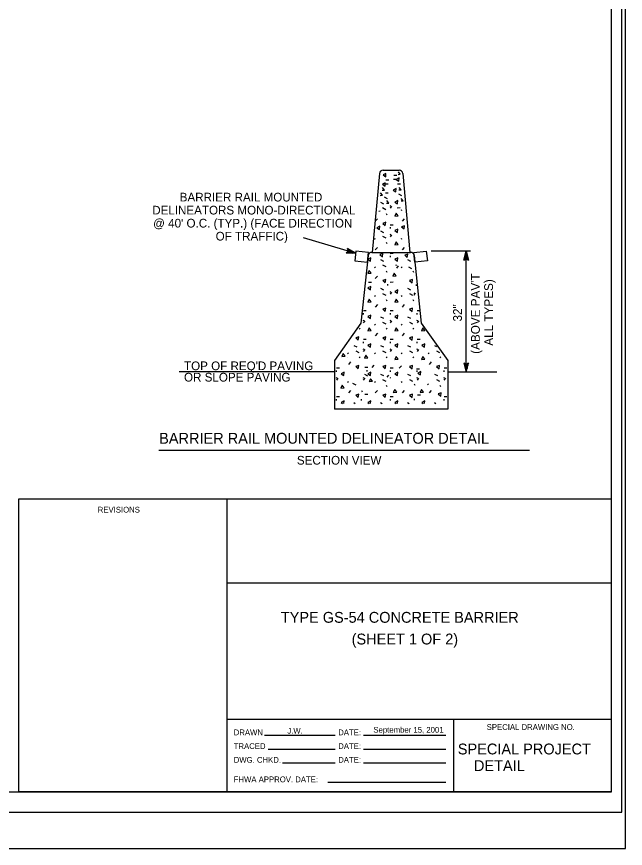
# Model space of a CAD drawing. Extents: x 504255 to 505955, y 659986 to 661086.
# Drawn here: x 505553 to 505955, y 659986 to 660536 of the extents above; entities that cross this region are included whole.
import ezdxf

# ---------------------------------------------------------------- set-up
doc = ezdxf.new("R2010")
doc.units = 0
for name, color, linetype in [('Level 62', 7, 'Continuous'), ('Level1', 7, 'Continuous'), ('Level3', 7, 'Continuous'), ('Level63', 7, 'Continuous')]:
    doc.layers.add(name, color=color, linetype=linetype)

msp = doc.modelspace()

# ---------------------------------------------------------------- linework, layer by layer
at = {"layer": 'Level 62'}
msp.add_lwpolyline([(505955.48, 661086.39), (504255.48, 661086.39), (504255.48, 659986.39), (505955.48, 659986.39)], close=True, dxfattribs=at)
at = {"layer": 'Level1'}
for p, q in [((505792.97, 660432.68), (505788.18, 660380.52)), ((505808.33, 660432.68), (505813.12, 660380.52)), ((505742.45, 660390.42), (505777.23, 660379.88)), ((505853.11, 660381.38), (505827.17, 660381.38)), ((505850.32, 660301.52), (505850.32, 660381.38)), ((505823.29, 660328.72), (505823.29, 660328.72)), ((505838.06, 660307.81), (505838.06, 660307.81)), ((505647.02, 660249.61), (505892.16, 660249.61)), ((505946.29, 660217.21), (505554.37, 660217.21)), ((505554.37, 660217.21), (505554.37, 660023.67)), ((505692.05, 660217.21), (505692.05, 660023.67)), ((505692.05, 660161.99), (505946.29, 660161.99)), ((505692.05, 660071.92), (505946.29, 660071.92)), ((505841.81, 660071.92), (505841.81, 660023.67)), ((505716.88, 660061.14), (505763.62, 660061.14)), ((505782.31, 660061.14), (505836.74, 660061.14)), ((505719.48, 660052.06), (505763.62, 660052.06)), ((505782.31, 660052.06), (505836.74, 660052.06)), ((505728.82, 660042.97), (505763.62, 660042.97)), ((505782.31, 660042.97), (505836.74, 660042.97)), ((505758.94, 660030.06), (505836.74, 660030.06)), ((505946.29, 660023.67), (505554.37, 660023.67))]:
    msp.add_line(p, q, dxfattribs=at)
for points in [[(504257.9, 660010.3), (505953.07, 660010.3), (505953.07, 661062.47), (504257.9, 661062.47), (504257.9, 660010.3)], [(504327.92, 660023.67), (505946.29, 660023.67), (505946.29, 661038.56), (504327.92, 661038.56), (504327.92, 660023.67)], [(505795.35, 660434.83), (505805.95, 660434.83)], [(505771.02, 660380.2), (505777.23, 660379.88), (505771.91, 660383.05), (505772.44, 660382.37), (505773.43, 660382.07), (505772.32, 660381.89), (505775.22, 660381.01), (505772.5, 660381.31), (505774.92, 660380.06), (505772.03, 660380.93), (505772.85, 660380.16), (505771.86, 660380.47), (505771.02, 660380.2), (505772.43, 660381.34), (505771.91, 660383.05)], [(505787.84, 660380.52), (505813.46, 660380.52)], [(505848.81, 660375.4), (505850.32, 660381.38), (505851.83, 660375.4), (505851.33, 660376.11), (505851.33, 660377.14), (505850.82, 660376.15), (505850.82, 660379.13), (505850.32, 660376.48), (505849.82, 660379.13), (505849.82, 660376.15), (505849.31, 660377.14), (505849.31, 660376.11), (505848.81, 660375.4), (505850.32, 660376.4), (505851.83, 660375.4)], [(505785.46, 660378.4), (505780.7, 660333.61)], [(505815.84, 660378.4), (505820.6, 660333.61)], [(505780.7, 660333.61), (505763.25, 660308.92)], [(505820.6, 660333.61), (505838.06, 660308.92)], [(505763.25, 660308.92), (505763.25, 660276.83)], [(505838.06, 660308.92), (505838.06, 660276.83)], [(505848.81, 660307.5), (505850.32, 660301.52), (505851.83, 660307.5), (505851.33, 660306.79), (505851.33, 660305.76), (505850.82, 660306.76), (505850.82, 660303.77), (505850.32, 660306.43), (505849.82, 660303.77), (505849.82, 660306.76), (505849.31, 660305.76), (505849.31, 660306.79), (505848.81, 660307.5), (505850.32, 660306.5), (505851.83, 660307.5)], [(505838.06, 660276.83), (505763.25, 660276.83)]]:
    msp.add_lwpolyline(points, dxfattribs=at)
for points in [[(505776.7, 660374.82), (505784.99, 660373.96), (505785.68, 660380.52), (505777.39, 660381.38)], [(505824.61, 660374.82), (505816.32, 660373.96), (505815.62, 660380.52), (505823.91, 660381.38)], [(505771.89, 660310.84), (505771.89, 660310.83), (505771.9, 660310.84)]]:
    msp.add_lwpolyline(points, close=True, dxfattribs=at)
for centre, start_param, end_param in [((505795.35, 660432.46), 4.712389, 6.192092), ((505805.95, 660432.46), 3.232686, 4.712389), ((505787.84, 660378.15), 4.712389, 6.178514), ((505813.46, 660378.15), 3.24706, 4.712389)]:
    msp.add_ellipse(centre, major_axis=(-2.39, 0), ratio=0.99, start_param=start_param, end_param=end_param, dxfattribs=at)
at = {"layer": 'Level3'}
for p, q in [((505804.37, 660431.35), (505802.41, 660431.32)), ((505798.81, 660425.58), (505796.85, 660425.55)), ((505799.08, 660428.33), (505797.12, 660428.3)), ((505804.1, 660428.78), (505802.14, 660428.74)), ((505806.79, 660425.67), (505804.83, 660425.64)), ((505798.81, 660419.73), (505796.85, 660419.69)), ((505805.62, 660419.24), (505807.58, 660418.09)), ((505793.7, 660413.71), (505795.7, 660412.65)), ((505796.04, 660417.26), (505798.03, 660416.21)), ((505792.64, 660407.68), (505793.34, 660408.01)), ((505795.02, 660410.17), (505797.08, 660408.96)), ((505800.57, 660411.03), (505799.98, 660411.21)), ((505801.02, 660411.03), (505800.02, 660409.64)), ((505806.61, 660409.87), (505804.65, 660409.84)), ((505807.36, 660408.39), (505808.07, 660408.72)), ((505791.55, 660402.75), (505790.17, 660401.15)), ((505797.35, 660406.23), (505797.77, 660405.37)), ((505809.32, 660402.75), (505807.95, 660401.15)), ((505799.98, 660397.11), (505799.98, 660396.22)), ((505802.04, 660398.6), (505800.08, 660398.56)), ((505793.7, 660394.77), (505795.7, 660393.71)), ((505795.02, 660391.23), (505797.08, 660390.02)), ((505800.57, 660392.1), (505799.98, 660392.26)), ((505801.02, 660392.1), (505800.02, 660390.7)), ((505789.59, 660389.45), (505790.3, 660389.78)), ((505797.35, 660387.29), (505797.77, 660386.43)), ((505807.36, 660389.45), (505808.07, 660389.78)), ((505791.55, 660383.81), (505790.17, 660382.21)), ((505802.04, 660379.66), (505800.08, 660379.63)), ((505809.32, 660383.81), (505807.95, 660382.21)), ((505793.7, 660375.83), (505795.7, 660374.77)), ((505799.98, 660378.17), (505799.98, 660377.28)), ((505811.49, 660375.83), (505813.47, 660374.77)), ((505789.59, 660370.51), (505790.3, 660370.83)), ((505795.02, 660372.29), (505797.08, 660371.09)), ((505804.35, 660371.81), (505803.76, 660371.99)), ((505805.3, 660371.49), (505804.3, 660370.1)), ((505807.36, 660370.51), (505808.07, 660370.83)), ((505812.1, 660371.03), (505814.16, 660369.83)), ((505791.55, 660364.87), (505790.17, 660363.27)), ((505797.35, 660368.35), (505797.77, 660367.49)), ((505815.12, 660368.35), (505815.54, 660367.49)), ((505787.64, 660360.6), (505785.67, 660360.56)), ((505798.36, 660359.46), (505798.36, 660358.58)), ((505802.04, 660360.72), (505800.08, 660360.68)), ((505817.31, 660359.19), (505817.31, 660358.3)), ((505793.7, 660356.89), (505795.7, 660355.83)), ((505795.02, 660353.34), (505797.08, 660352.14)), ((505800.57, 660354.22), (505799.98, 660354.39)), ((505801.02, 660354.22), (505800.02, 660352.83)), ((505811.49, 660356.89), (505813.47, 660355.83)), ((505812.8, 660353.34), (505814.86, 660352.14)), ((505816.64, 660353.42), (505815.65, 660352.03)), ((505816.38, 660353.33), (505815.79, 660353.5)), ((505789.59, 660351.57), (505790.3, 660351.89)), ((505797.35, 660349.41), (505797.77, 660348.55)), ((505807.36, 660351.57), (505808.07, 660351.89)), ((505815.12, 660349.41), (505815.54, 660348.55)), ((505784.27, 660341.78), (505782.31, 660341.74)), ((505791.55, 660345.93), (505790.17, 660344.33)), ((505802.04, 660341.78), (505800.08, 660341.74)), ((505809.32, 660345.93), (505807.95, 660344.33)), ((505819.82, 660341.78), (505817.86, 660341.74)), ((505782.21, 660340.29), (505782.21, 660339.4)), ((505793.7, 660337.95), (505795.7, 660336.89)), ((505799.98, 660340.29), (505799.98, 660339.4)), ((505811.49, 660337.95), (505813.47, 660336.89)), ((505817.76, 660340.29), (505817.76, 660339.4)), ((505779.57, 660330.47), (505779.99, 660329.61)), ((505782.8, 660335.27), (505782.21, 660335.45)), ((505783.24, 660335.27), (505782.25, 660333.88)), ((505789.59, 660332.63), (505790.3, 660332.95)), ((505795.02, 660334.4), (505797.08, 660333.2)), ((505797.35, 660330.47), (505797.77, 660329.61)), ((505800.57, 660335.27), (505799.98, 660335.45)), ((505801.02, 660335.27), (505800.02, 660333.88)), ((505807.36, 660332.63), (505808.07, 660332.95)), ((505812.8, 660334.4), (505814.86, 660333.2)), ((505815.12, 660330.47), (505815.54, 660329.61)), ((505818.35, 660335.27), (505817.76, 660335.45)), ((505818.79, 660335.27), (505817.8, 660333.88)), ((505791.55, 660326.99), (505790.17, 660325.39)), ((505809.32, 660326.99), (505807.95, 660325.39)), ((505775.93, 660319.01), (505777.92, 660317.96)), ((505782.21, 660321.35), (505782.21, 660320.47)), ((505784.27, 660322.84), (505782.31, 660322.8)), ((505793.7, 660319.01), (505795.7, 660317.96)), ((505799.98, 660321.35), (505799.98, 660320.47)), ((505802.04, 660322.84), (505800.08, 660322.8)), ((505811.49, 660319.01), (505813.47, 660317.96)), ((505817.76, 660321.35), (505817.76, 660320.47)), ((505819.82, 660322.84), (505817.86, 660322.8)), ((505829.26, 660319.01), (505830.68, 660318.25)), ((505771.81, 660313.7), (505772.51, 660314.01)), ((505777.25, 660315.46), (505779.31, 660314.26)), ((505782.8, 660316.34), (505782.21, 660316.51)), ((505783.24, 660316.34), (505782.25, 660314.94)), ((505789.59, 660313.7), (505790.3, 660314.01)), ((505795.02, 660315.46), (505797.08, 660314.26)), ((505800.57, 660316.34), (505799.98, 660316.51)), ((505801.02, 660316.34), (505800.02, 660314.94)), ((505807.36, 660313.7), (505808.07, 660314.01)), ((505812.8, 660315.46), (505814.86, 660314.26)), ((505818.35, 660316.34), (505817.76, 660316.51)), ((505818.79, 660316.34), (505817.8, 660314.94)), ((505825.14, 660313.7), (505825.84, 660314.01)), ((505830.58, 660315.46), (505832.63, 660314.26)), ((505773.77, 660308.05), (505772.4, 660306.45)), ((505779.57, 660311.53), (505779.99, 660310.67)), ((505797.35, 660311.53), (505797.77, 660310.67)), ((505815.12, 660311.53), (505815.54, 660310.67)), ((505827.09, 660308.05), (505825.73, 660306.45)), ((505832.9, 660311.53), (505833.32, 660310.67)), ((505766.49, 660303.9), (505764.53, 660303.86)), ((505785.33, 660304.34), (505783.37, 660304.3)), ((505784.58, 660302.54), (505784.58, 660301.65)), ((505789.32, 660305.94), (505787.95, 660304.34)), ((505802.04, 660303.9), (505800.08, 660303.86)), ((505807.46, 660305.5), (505806.08, 660303.9)), ((505819.46, 660303.26), (505817.49, 660303.22)), ((505837.59, 660303.9), (505835.63, 660303.86)), ((505764.43, 660302.41), (505764.43, 660301.52)), ((505765.02, 660297.4), (505764.43, 660297.57)), ((505765.47, 660297.4), (505764.48, 660296)), ((505782.8, 660297.4), (505782.21, 660297.57)), ((505783.24, 660297.4), (505782.25, 660296)), ((505783, 660300.01), (505784.99, 660298.95)), ((505793.7, 660300.07), (505795.7, 660299.02)), ((505798.85, 660299.32), (505797.86, 660297.93)), ((505799.98, 660302.41), (505799.98, 660301.52)), ((505800.57, 660297.4), (505799.98, 660297.57)), ((505811.49, 660300.07), (505813.47, 660299.02)), ((505817.76, 660302.41), (505817.76, 660301.52)), ((505818.35, 660297.4), (505817.76, 660297.57)), ((505818.79, 660297.4), (505817.8, 660296)), ((505829.26, 660300.07), (505831.25, 660299.02)), ((505835.53, 660302.41), (505835.53, 660301.52)), ((505836.13, 660297.4), (505835.53, 660297.57)), ((505836.57, 660297.4), (505835.58, 660296)), ((505771.81, 660294.75), (505772.51, 660295.08)), ((505775.23, 660294.02), (505777.29, 660292.81)), ((505789.59, 660294.75), (505790.3, 660295.08)), ((505795.02, 660296.53), (505797.08, 660295.32)), ((505797.35, 660292.59), (505797.77, 660291.73)), ((505807.36, 660294.75), (505808.07, 660295.08)), ((505812.8, 660296.53), (505814.86, 660295.32)), ((505815.81, 660293.5), (505816.23, 660292.63)), ((505824.68, 660293.16), (505825.39, 660293.49)), ((505830.58, 660296.53), (505832.63, 660295.32)), ((505832.9, 660292.59), (505833.32, 660291.73)), ((505773.77, 660289.11), (505772.4, 660287.52)), ((505781.06, 660289.2), (505781.48, 660288.33)), ((505785.27, 660286.52), (505783.31, 660286.47)), ((505791.55, 660289.11), (505790.17, 660287.52)), ((505809.32, 660289.11), (505807.95, 660287.52)), ((505820.03, 660286.06), (505818.07, 660286.02)), ((505827.09, 660289.11), (505825.73, 660287.52)), ((505764.43, 660283.47), (505764.43, 660282.58)), ((505766.49, 660284.96), (505764.53, 660284.92)), ((505775.93, 660281.13), (505776.92, 660280.61)), ((505780.96, 660283.34), (505780.96, 660282.45)), ((505793.7, 660281.13), (505794.7, 660280.61)), ((505799.98, 660283.47), (505799.98, 660282.58)), ((505802.04, 660284.96), (505800.08, 660284.92)), ((505811.49, 660281.13), (505812.48, 660280.61)), ((505815.96, 660283.67), (505815.96, 660282.79)), ((505829.26, 660281.13), (505830.25, 660280.61)), ((505835.53, 660283.47), (505835.53, 660282.58)), ((505837.59, 660284.96), (505835.63, 660284.92))]:
    msp.add_line(p, q, dxfattribs=at)
for points in [[(505795.32, 660431.74), (505797.06, 660430.55), (505797.27, 660432.75)], [(505803.92, 660428.73), (505805.66, 660427.53), (505805.88, 660429.74)], [(505794.87, 660425.53), (505796.62, 660424.34), (505796.83, 660426.54)], [(505801.95, 660421.72), (505803.69, 660420.52), (505803.91, 660422.72)], [(505803.11, 660413.81), (505804.86, 660412.62), (505805.08, 660414.82)], [(505803.92, 660406.32), (505803.03, 660404.4), (505805.26, 660404.56)], [(505791.17, 660396.83), (505792.91, 660395.64), (505793.12, 660397.84)], [(505797.11, 660400.37), (505795.11, 660399.7), (505796.76, 660398.21)], [(505809.6, 660398.15), (505807.58, 660397.48), (505809.24, 660395.99)], [(505803.11, 660394.88), (505804.86, 660393.68), (505805.08, 660395.88)], [(505803.92, 660387.38), (505803.03, 660385.46), (505805.26, 660385.63)], [(505795.25, 660379.7), (505793.25, 660379.02), (505794.91, 660377.53)], [(505785.34, 660375.94), (505787.08, 660374.74), (505787.3, 660376.94)], [(505803.11, 660375.94), (505804.86, 660374.74), (505805.08, 660376.94)], [(505811.66, 660379.3), (505809.65, 660378.62), (505811.31, 660377.14)], [(505786.15, 660368.43), (505785.25, 660366.52), (505787.48, 660366.7)], [(505802.68, 660366.69), (505801.79, 660364.78), (505804.02, 660364.95)], [(505785.34, 660357), (505787.08, 660355.81), (505787.3, 660358)], [(505797.11, 660362.49), (505795.11, 660361.82), (505796.76, 660360.33)], [(505814.89, 660362.49), (505812.88, 660361.82), (505814.54, 660360.33)], [(505803.22, 660354.63), (505804.96, 660353.44), (505805.18, 660355.64)], [(505786.15, 660349.5), (505785.25, 660347.58), (505787.48, 660347.75)], [(505803.92, 660349.5), (505803.03, 660347.58), (505805.26, 660347.75)], [(505797.11, 660343.56), (505795.11, 660342.88), (505796.76, 660341.4)], [(505814.89, 660343.56), (505812.88, 660342.88), (505814.54, 660341.4)], [(505785.34, 660338.05), (505787.08, 660336.86), (505787.3, 660339.06)], [(505803.11, 660338.05), (505804.86, 660336.86), (505805.08, 660339.06)], [(505786.15, 660330.55), (505785.25, 660328.65), (505787.48, 660328.81)], [(505803.92, 660330.55), (505803.03, 660328.65), (505805.26, 660328.81)], [(505821.7, 660330.55), (505820.8, 660328.65), (505823.03, 660328.81)], [(505779.34, 660324.61), (505777.33, 660323.94), (505778.99, 660322.46)], [(505797.11, 660324.61), (505795.11, 660323.94), (505796.76, 660322.46)], [(505814.89, 660324.61), (505812.88, 660323.94), (505814.54, 660322.46)], [(505785.34, 660319.12), (505787.08, 660317.92), (505787.3, 660320.12)], [(505803.11, 660319.12), (505804.86, 660317.92), (505805.08, 660320.12)], [(505820.89, 660319.12), (505822.64, 660317.92), (505822.85, 660320.12)], [(505769.01, 660313.6), (505768.12, 660311.7), (505770.35, 660311.86)], [(505783.89, 660312.5), (505783, 660310.6), (505785.22, 660310.76)], [(505803.92, 660311.61), (505803.03, 660309.71), (505805.26, 660309.87)], [(505821.7, 660311.61), (505820.8, 660309.71), (505823.03, 660309.87)], [(505779.34, 660305.67), (505777.33, 660305), (505778.99, 660303.51)], [(505797.11, 660305.67), (505795.11, 660305), (505796.76, 660303.51)], [(505814.89, 660305.67), (505812.88, 660305), (505814.54, 660303.51)], [(505832.66, 660305.67), (505830.65, 660305), (505832.31, 660303.51)], [(505767.56, 660300.17), (505769.31, 660298.98), (505769.52, 660301.18)], [(505785.34, 660300.17), (505787.08, 660298.98), (505787.3, 660301.18)], [(505803.11, 660300.17), (505804.86, 660298.98), (505805.08, 660301.18)], [(505818.34, 660300.63), (505820.08, 660299.44), (505820.3, 660301.64)], [(505768.37, 660292.68), (505767.48, 660290.77), (505769.71, 660290.93)], [(505787.06, 660296.98), (505786.17, 660295.07), (505788.39, 660295.23)], [(505779.34, 660286.73), (505777.33, 660286.06), (505778.99, 660284.57)], [(505797.11, 660286.73), (505795.11, 660286.06), (505796.76, 660284.57)], [(505803.01, 660289.84), (505802.11, 660287.94), (505804.35, 660288.1)], [(505814.89, 660286.73), (505812.88, 660286.06), (505814.54, 660284.57)], [(505820.67, 660289.84), (505819.78, 660287.94), (505822.01, 660288.1)], [(505833.84, 660287.56), (505831.83, 660286.89), (505833.49, 660285.4)]]:
    msp.add_lwpolyline(points, close=True, dxfattribs=at)
for points in [[(505805.32, 660432.07), (505806.75, 660432.18), (505805.51, 660433.8)], [(505805.86, 660421.78), (505807.28, 660421.88), (505806.04, 660423.5)], [(505793.5, 660418.14), (505794.92, 660418.24), (505793.68, 660419.86)], [(505794.84, 660421.6), (505796.26, 660421.7), (505795.02, 660423.33)], [(505797.62, 660412.99), (505799.04, 660413.09), (505797.8, 660414.72)], [(505807.21, 660414.5), (505808.63, 660414.6), (505807.39, 660416.22)], [(505769.36, 660280.61), (505769.52, 660282.24), (505767.56, 660281.24), (505768.48, 660280.61)], [(505787.14, 660280.61), (505787.3, 660282.24), (505785.34, 660281.24), (505786.26, 660280.61)], [(505804.91, 660280.61), (505805.08, 660282.24), (505803.11, 660281.24), (505804.04, 660280.61)], [(505822.69, 660280.61), (505822.85, 660282.24), (505820.89, 660281.24), (505821.81, 660280.61)]]:
    msp.add_lwpolyline(points, dxfattribs=at)
at = {"layer": 'Level63'}
for p, q in [((505763.25, 660301.52), (505660.67, 660301.52)), ((505838.06, 660301.52), (505870.56, 660301.52)), ((505787.16, 660280.61), (505787.16, 660280.61)), ((505838.06, 660280.61), (505838.06, 660280.61))]:
    msp.add_line(p, q, dxfattribs=at)

# ---------------------------------------------------------------- texts
at = {"layer": 'Level1'}
for s, height, p in [('BARRIER RAIL MOUNTED', 5.7394, (505660.93, 660414.16)), ('DELINEATORS MONO-DIRECTIONAL', 5.7394, (505642.76, 660405.55)), ("@ 40' O.C. (TYP.) (FACE DIRECTION", 5.7394, (505643.37, 660396.94)), ('OF TRAFFIC)', 5.7394, (505684.7, 660388.33)), ("TOP OF REQ'D PAVING ", 5.7392, (505663.79, 660302.61)), ('OR SLOPE PAVING', 5.7392, (505663.79, 660295.08)), ('BARRIER RAIL MOUNTED DELINEATOR DETAIL', 7.1744, (505647.35, 660253.98)), ('SECTION VIEW', 5.7395, (505738.38, 660240.17)), ('REVISIONS', 3.826, (505606.77, 660208.42)), ('TYPE GS-54 CONCRETE BARRIER', 7.1739, (505727.76, 660135.57)), ('(SHEET 1 OF 2)', 7.1739, (505774.57, 660121.22)), ('J.W.', 3.826, (505732.04, 660062.24)), ('September 15, 2001', 3.8261, (505788.95, 660062.86)), ('SPECIAL DRAWING NO.', 3.8261, (505863.83, 660064.7)), ('DRAWN', 3.826, (505696.63, 660061.17)), ('DATE:', 3.826, (505765.7, 660061.17)), ('TRACED', 3.826, (505696.63, 660052.09)), ('DATE:', 3.826, (505765.7, 660052.09)), ('SPECIAL PROJECT', 7.1739, (505844.75, 660048.51)), ('DWG. CHKD.', 3.826, (505696.63, 660043)), ('DATE:', 3.826, (505765.7, 660043)), ('    DETAIL', 7.174, (505844.75, 660037.51)), ('FHWA APPROV. DATE:', 3.8261, (505696.63, 660030.09))]:
    msp.add_text(s, height=height, dxfattribs=at).set_placement(p)
for s, height, p in [("(ABOVE PAV'T", 5.7971, (505859.29, 660313.42)), ('ALL TYPES)', 5.797, (505867.99, 660318.79)), ('32"', 5.797, (505847.44, 660334.79))]:
    msp.add_text(s, height=height, rotation=90, dxfattribs=at).set_placement(p)

doc.saveas('drawing.dxf')
